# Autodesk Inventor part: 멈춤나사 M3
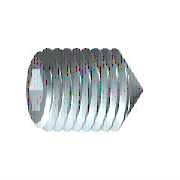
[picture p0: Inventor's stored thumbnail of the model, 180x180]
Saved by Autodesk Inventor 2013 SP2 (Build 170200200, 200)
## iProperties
Created: 2012-02
Part Number: 멈춤나사 M3
Material: 강철, 연강
Description: 6각 소켓 머리 없는 멈춤 나사
Document SubType Name: Modeling
Standard: KS B 1028
Designer: mduedu
Standards Organization: KS
Language: ko-KR
Size Designation: 원추점 M3x8
Categories: <MemberInstance><Categories><Category DisplayName="조임쇠" InternalName="e4da775c-781d-43d5-af7c-5136215cf5a6" Mnemonic="FSTN"><Category DisplayName="볼트" InternalN
Density: 7.86 g/cm^3
Mass: 0.360339 g
Surface Area: 0.888172 cm^2
Volume: 0.0458447 cm^3
IsCustomPart: 1
Author: mduedu
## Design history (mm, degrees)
sketch "스케치1"
  geometry: L1 (0, 0)-(5.5, 0); L2 (8, 0.866)-(8, 1.5); L3 (8, 1.5)-(0, 1.5); L4 (8, 0.866)-(6, 0.866); L5 (6, 0.866)-(5.5, 0); L6 (0, -0.3)-(0, 1.8) reference; L7 (0, 1.5)-(0, 0)
  constraints: 13 end point, 3 parallel, 1 collinear, 1 perpendicular, 1 point on line
  dimensions: "d0" = 2 distance of L2.start L4.end (= INTI); "d1" = 60 deg angle of L5 L1; "d2" = 3 diameter of L3 L1 (= NND); "d3" = 1.73205 diameter of L4 L1 (= 1.1547 x SW); "d5" = 8 distance from line of L2 L3.end (= NLG)
revolve "본체" sketch "스케치1" stored, may be unused: angle "d6" = 90 deg
sketch "스케치2"
  geometry: L1 (-0.433, 0.75)-(0.433, 0.75); L2 (0.433, 0.75)-(0.866, 0); L3 (0.866, 0)-(0.433, -0.75); L4 (0.433, -0.75)-(-0.433, -0.75); L5 (-0.433, -0.75)-(-0.866, 0); L6 (-0.866, 0)-(-0.433, 0.75); 3 further points
  constraints: 12 end point, 1 coincident, 1 horizontal, 13 other
extrude "슬롯" join sketch "스케치2" taper "d7" = 0 deg; stored distance "d21" = 10
workaxis "Work Axis1"
workplane "Work Plane1"
sketch "스케치5"
  geometry: L1 (-4, -0.15)-(-2.65, -1.5) reference; L2 (-4, 0.15)-(-2.65, 1.5) reference; L3 (-2.65, 1.5)-(-4.15, 0); L4 (-2.65, -1.5)-(-4.15, 0); 1 further point
  constraints: 4 end point, 1 horizontal alignment, 1 perpendicular
node "작업점1"
body "Solid1"
feature "스레드" dims "d12" = 8 (= NLG), "d13" = 0
chamfer "모따기1" distance "d8" = 1.35 (computed from NND, SPD, FAWI); stored, may be unused: angle "d9" = 45 deg (= FAWI), second distance "d34" = 1.35 (computed from NND, SPD, FAWI)
chamfer "모따기2" distance "d10" = 0.30673 (= -0.5 x GD1 + 0.5 x NND); stored, may be unused: angle "d11" = 45 deg (= FAWI), second distance "d35" = 0.30673 (= -0.5 x GD1 + 0.5 x NND)
other parameters: "NND" = 3 [user parameter; used in 5 equation terms], "NLG" = 8 [user parameter; used in 2 equation terms], "INTI" = 2 [user parameter; used in 1 equation term], "FAWI" = 45 deg [user parameter; used in 4 equation terms], "SW" = 1.5 [user parameter; used in 2 equation terms], "GD1" = 2.38655 (= THREADDIA - 1.2269 x PTC) [user parameter; used in 2 equation terms], "d4" = 0, "FAWI1" = 45 deg [user parameter], "SPD" = 0.3 [user parameter; used in 2 equation terms], "d36" = 0, "d37" = 0, "GUL" = 0.30673 (= 0.61345 x PTC) [user parameter], "TOA" = 30 deg [user parameter], "THREADDIA" = 3 [user parameter; used in 1 equation term], "PTC" = 0.5 [user parameter; used in 4 equation terms], "GAL" = 0.30673 (= 0.61345 x PTC) [user parameter], "E0" = 1.7325 (= 1.155 x SW) [user parameter]
